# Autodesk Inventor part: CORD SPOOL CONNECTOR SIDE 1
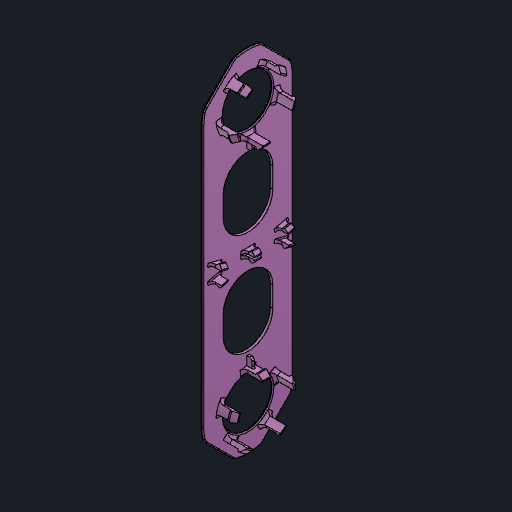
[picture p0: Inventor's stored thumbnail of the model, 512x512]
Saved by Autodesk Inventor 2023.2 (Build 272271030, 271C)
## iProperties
Created: 2022-11
Part Number: CORD SPOOL CONNECTOR SIDE 1
Material: Generic
Document SubType Name: Modeling
Designer: AR
Mass: 27.4073 g
Surface Area: 293.122 cm^2
Volume: 27.4073 cm^3
Density: 1 g/cm^3
Appearance: Smooth - Light Orange
Author: AR
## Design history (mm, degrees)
derived "_2 SPOOL CORD WRAP MP.ipt"
workaxis "Work Axis1"
  workplane "Work Plane1"
feature "PRUSA CORD SPOOL CONNECTOR SIDE 1::_2 SPOOL CORD WRAP MP.ipt" dims "d0" = 10
tag "TaggingFeature1"
node "PRUSA CORD SPOOL CONNECTOR SIDE 1"
